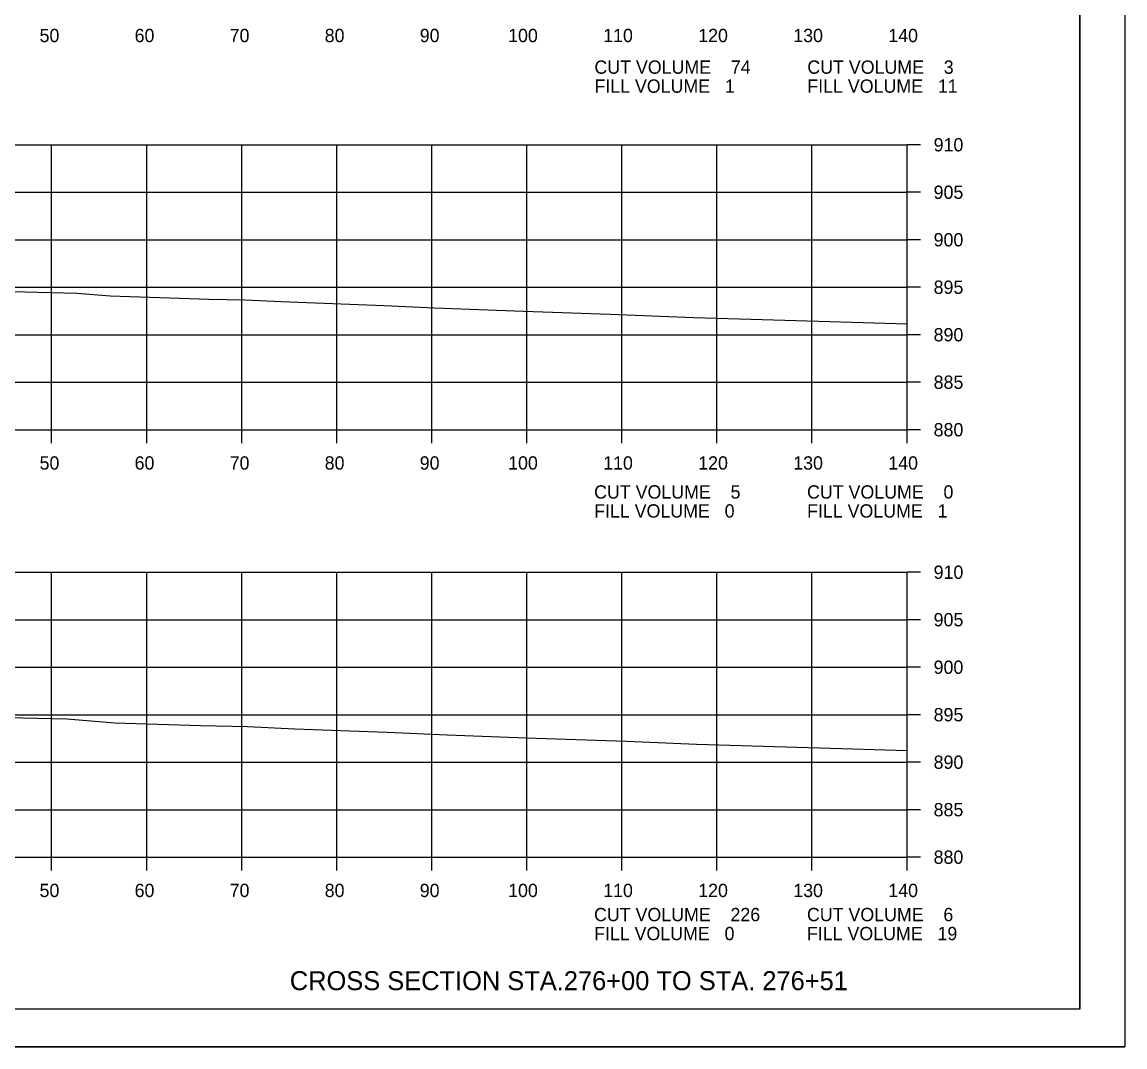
# Model space of a CAD drawing. Extents: x 1486524 to 1499135, y 326561 to 337924.
# Drawn here: x 1489029.8 to 1489145.8, y 331072.6 to 331180.5 of the extents above; entities that cross this region are included whole.
import ezdxf

# ---------------------------------------------------------------- set-up
doc = ezdxf.new("R2010")
doc.units = 0
for name, color, linetype in [('E_Const Align', 7, 'Continuous'), ('E_Const Align Station', 7, 'Continuous'), ('E_Ownership Information', 7, 'Continuous'), ('E_Property Line', 7, 'Continuous'), ('E_Proposed ROW Fig Annot', 7, 'Continuous'), ('E_Quarter Calls', 7, 'Continuous'), ('E_Tract Number', 7, 'Continuous')]:
    doc.layers.add(name, color=color, linetype=linetype)

msp = doc.modelspace()

# ---------------------------------------------------------------- linework, layer by layer
at = {"layer": 'E_Const Align'}
for p, q in [((1489122.89, 331137.58), (1489122.89, 331167.58)), ((1489124.29, 331167.58), (1489122.89, 331167.58)), ((1489124.29, 331162.58), (1489122.89, 331162.58)), ((1489124.29, 331157.58), (1489122.89, 331157.58)), ((1489124.29, 331152.58), (1489122.89, 331152.58)), ((1489124.29, 331147.58), (1489122.89, 331147.58)), ((1489124.29, 331142.58), (1489122.89, 331142.58)), ((1488842.89, 331137.58), (1489122.89, 331137.58)), ((1489032.89, 331136.18), (1489032.89, 331137.58)), ((1489042.89, 331136.18), (1489042.89, 331137.58)), ((1489052.89, 331136.18), (1489052.89, 331137.58)), ((1489062.89, 331136.18), (1489062.89, 331137.58)), ((1489072.89, 331136.18), (1489072.89, 331137.58)), ((1489082.89, 331136.18), (1489082.89, 331137.58)), ((1489092.89, 331136.18), (1489092.89, 331137.58)), ((1489102.89, 331136.18), (1489102.89, 331137.58)), ((1489112.89, 331136.18), (1489112.89, 331137.58)), ((1489122.89, 331136.18), (1489122.89, 331137.58)), ((1489124.29, 331137.58), (1489122.89, 331137.58)), ((1489122.89, 331092.58), (1489122.89, 331122.58)), ((1489124.29, 331122.58), (1489122.89, 331122.58)), ((1489124.29, 331117.58), (1489122.89, 331117.58)), ((1489124.29, 331112.58), (1489122.89, 331112.58)), ((1489124.29, 331107.58), (1489122.89, 331107.58)), ((1489124.29, 331102.58), (1489122.89, 331102.58)), ((1489124.29, 331097.58), (1489122.89, 331097.58)), ((1488842.89, 331092.58), (1489122.89, 331092.58)), ((1489032.89, 331091.18), (1489032.89, 331092.58)), ((1489042.89, 331091.18), (1489042.89, 331092.58)), ((1489052.89, 331091.18), (1489052.89, 331092.58)), ((1489062.89, 331091.18), (1489062.89, 331092.58)), ((1489072.89, 331091.18), (1489072.89, 331092.58)), ((1489082.89, 331091.18), (1489082.89, 331092.58)), ((1489092.89, 331091.18), (1489092.89, 331092.58)), ((1489102.89, 331091.18), (1489102.89, 331092.58)), ((1489112.89, 331091.18), (1489112.89, 331092.58)), ((1489122.89, 331091.18), (1489122.89, 331092.58)), ((1489124.29, 331092.58), (1489122.89, 331092.58))]:
    msp.add_line(p, q, dxfattribs=at)
at = {"layer": 'E_Ownership Information'}
for p, q in [((1488842.89, 331167.58), (1489122.89, 331167.58)), ((1489032.89, 331137.58), (1489032.89, 331167.58)), ((1489042.89, 331137.58), (1489042.89, 331167.58)), ((1489052.89, 331137.58), (1489052.89, 331167.58)), ((1489062.89, 331137.58), (1489062.89, 331167.58)), ((1489072.89, 331137.58), (1489072.89, 331167.58)), ((1489082.89, 331137.58), (1489082.89, 331167.58)), ((1489092.89, 331137.58), (1489092.89, 331167.58)), ((1489102.89, 331137.58), (1489102.89, 331167.58)), ((1489112.89, 331137.58), (1489112.89, 331167.58)), ((1489122.89, 331137.58), (1489122.89, 331167.58)), ((1488842.89, 331162.58), (1489122.89, 331162.58)), ((1488842.89, 331157.58), (1489122.89, 331157.58)), ((1488842.89, 331152.58), (1489122.89, 331152.58)), ((1488842.89, 331147.58), (1489122.89, 331147.58)), ((1488842.89, 331142.58), (1489122.89, 331142.58)), ((1488842.89, 331137.58), (1489122.89, 331137.58)), ((1488842.89, 331122.58), (1489122.89, 331122.58)), ((1489032.89, 331092.58), (1489032.89, 331122.58)), ((1489042.89, 331092.58), (1489042.89, 331122.58)), ((1489052.89, 331092.58), (1489052.89, 331122.58)), ((1489062.89, 331092.58), (1489062.89, 331122.58)), ((1489072.89, 331092.58), (1489072.89, 331122.58)), ((1489082.89, 331092.58), (1489082.89, 331122.58)), ((1489092.89, 331092.58), (1489092.89, 331122.58)), ((1489102.89, 331092.58), (1489102.89, 331122.58)), ((1489112.89, 331092.58), (1489112.89, 331122.58)), ((1489122.89, 331092.58), (1489122.89, 331122.58)), ((1488842.89, 331117.58), (1489122.89, 331117.58)), ((1488842.89, 331112.58), (1489122.89, 331112.58)), ((1488842.89, 331107.58), (1489122.89, 331107.58)), ((1488842.89, 331102.58), (1489122.89, 331102.58)), ((1488842.89, 331097.58), (1489122.89, 331097.58)), ((1488842.89, 331092.58), (1489122.89, 331092.58))]:
    msp.add_line(p, q, dxfattribs=at)
at = {"layer": 'E_Property Line'}
for q in [(1489141.07, 331282.04), (1488824.89, 331076.58)]:
    msp.add_line((1489141.07, 331076.58), q, dxfattribs=at)
at = {"layer": 'E_Quarter Calls'}
msp.add_line((1488812.48, 331072.61), (1489145.82, 331072.61), dxfattribs=at)
for points in [[(1488812.48, 331285.94), (1489145.82, 331285.94), (1489145.82, 331072.6), (1488812.48, 331072.6)], [(1489058.81, 331282.04), (1489058.81, 331272.16), (1489094.54, 331272.16), (1489094.54, 331269.24), (1489117.74, 331269.24), (1489117.74, 331244.91), (1489141.07, 331244.91), (1489141.07, 331076.58), (1488824.89, 331076.58), (1488824.89, 331282.04)]]:
    msp.add_lwpolyline(points, close=True, dxfattribs=at)
at = {"layer": 'E_Tract Number'}
for points in [[(1489024.48, 331152.22), (1489035.57, 331151.94), (1489039.06, 331151.66), (1489049.43, 331151.33), (1489053.21, 331151.24), (1489057.05, 331151.07), (1489067.89, 331150.66), (1489073.16, 331150.42), (1489082.55, 331150.06), (1489091.65, 331149.76), (1489100.47, 331149.41), (1489108.83, 331149.15), (1489113.56, 331148.99), (1489122.89, 331148.71)], [(1489025.17, 331107.37), (1489034.48, 331107.13), (1489039.54, 331106.74), (1489048.6, 331106.45), (1489053.49, 331106.33), (1489058.47, 331106.1), (1489068.16, 331105.74), (1489074.52, 331105.45), (1489082.81, 331105.13), (1489093.36, 331104.79), (1489100.73, 331104.49), (1489110.1, 331104.21), (1489113.68, 331104.08), (1489122.89, 331103.81)]]:
    msp.add_lwpolyline(points, dxfattribs=at)

# ---------------------------------------------------------------- texts
at = {"layer": 'E_Const Align Station'}
for s, p in [('50', (1489031.62, 331178.38)), ('60', (1489041.62, 331178.38)), ('70', (1489051.62, 331178.38)), ('80', (1489061.62, 331178.38)), ('90', (1489071.62, 331178.38)), ('100', (1489080.92, 331178.38)), ('110', (1489090.92, 331178.38)), ('120', (1489100.92, 331178.38)), ('130', (1489110.92, 331178.38)), ('140', (1489120.92, 331178.38)), ('CUT VOLUME    74', (1489090, 331175.05)), ('CUT VOLUME    3', (1489112.4, 331175.05)), ('FILL VOLUME   1', (1489090, 331173.05)), ('FILL VOLUME   11', (1489112.4, 331173.05)), ('910', (1489125.69, 331166.88)), ('905', (1489125.69, 331161.88)), ('900', (1489125.69, 331156.88)), ('895', (1489125.69, 331151.88)), ('890', (1489125.69, 331146.88)), ('885', (1489125.69, 331141.88)), ('880', (1489125.69, 331136.88)), ('50', (1489031.62, 331133.38)), ('60', (1489041.62, 331133.38)), ('70', (1489051.62, 331133.38)), ('80', (1489061.62, 331133.38)), ('90', (1489071.62, 331133.38)), ('100', (1489080.92, 331133.38)), ('110', (1489090.92, 331133.38)), ('120', (1489100.92, 331133.38)), ('130', (1489110.92, 331133.38)), ('140', (1489120.92, 331133.38)), ('CUT VOLUME    5', (1489089.97, 331130.33)), ('CUT VOLUME    0', (1489112.37, 331130.33)), ('FILL VOLUME   0', (1489089.97, 331128.33)), ('FILL VOLUME   1', (1489112.37, 331128.33)), ('910', (1489125.69, 331121.88)), ('905', (1489125.69, 331116.88)), ('900', (1489125.69, 331111.88)), ('895', (1489125.69, 331106.88)), ('890', (1489125.69, 331101.88)), ('885', (1489125.69, 331096.88)), ('880', (1489125.69, 331091.88)), ('50', (1489031.62, 331088.38)), ('60', (1489041.62, 331088.38)), ('70', (1489051.62, 331088.38)), ('80', (1489061.62, 331088.38)), ('90', (1489071.62, 331088.38)), ('100', (1489080.92, 331088.38)), ('110', (1489090.92, 331088.38)), ('120', (1489100.92, 331088.38)), ('130', (1489110.92, 331088.38)), ('140', (1489120.92, 331088.38)), ('CUT VOLUME    226 ', (1489089.96, 331085.84)), ('CUT VOLUME    6', (1489112.36, 331085.84)), ('FILL VOLUME   0', (1489089.96, 331083.84)), ('FILL VOLUME   19', (1489112.36, 331083.84))]:
    msp.add_text(s, height=1.4, dxfattribs=at).set_placement(p)
at = {"layer": 'E_Proposed ROW Fig Annot'}
msp.add_text('CROSS SECTION STA.276+00 TO STA. 276+51', height=2, dxfattribs=at).set_placement((1489057.95, 331078.58))

doc.saveas('drawing.dxf')
